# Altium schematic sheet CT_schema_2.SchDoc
size 176 x 147 mm
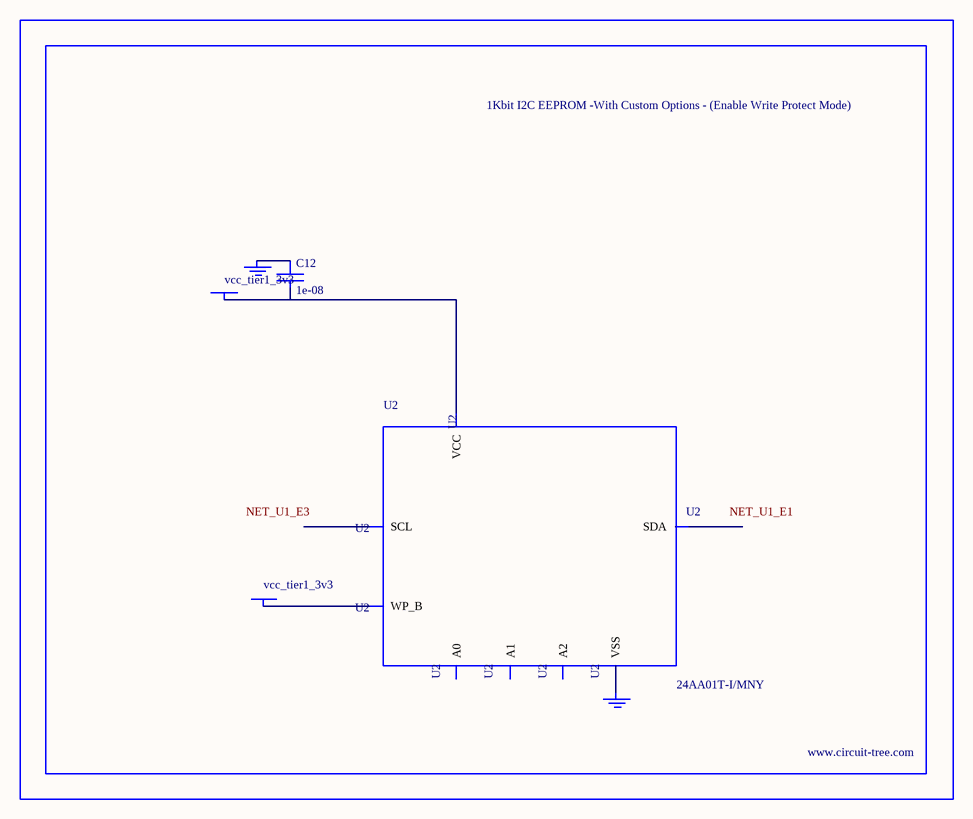
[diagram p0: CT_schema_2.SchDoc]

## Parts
BORDER1  (no value)
C12  1e-08  [C0402]
GND_INSTANCE_1_0  (no value)
GND_INSTANCE_1_1  (no value)
POWER_INSTANCE_1_0  vcc_tier1_3v3
POWER_INSTANCE_1_1  vcc_tier1_3v3
U2  24AA01T-I/MNY  [TDFN-8/6MM]

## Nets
NetC12_1: C12.1 GND_INSTANCE_1_0.0(GND)
NetC12_2: C12.2 POWER_INSTANCE_1_1.0(PWR) U2.8(VCC)
NetGND_INSTANCE_1_1_0: GND_INSTANCE_1_1.0(GND) U2.4(VSS)
NetPOWER_INSTANCE_1_0_0: POWER_INSTANCE_1_0.0(PWR) U2.7(WP_B)

Not connected (* = marked no-connect by the designer): U2 1(A0) 2(A1) 3(A2) 5(SDA) 6(SCL)

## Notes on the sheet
- Labels drawn without touching a wire or pin: NET_U1_E1, NET_U1_E3

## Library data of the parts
BORDER1 = BORDER_PAGE1
C12 = C0402C103K3RAC
GND_INSTANCE_1_0 GND_INSTANCE_1_1 = GND
POWER_INSTANCE_1_0 POWER_INSTANCE_1_1 = PWR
